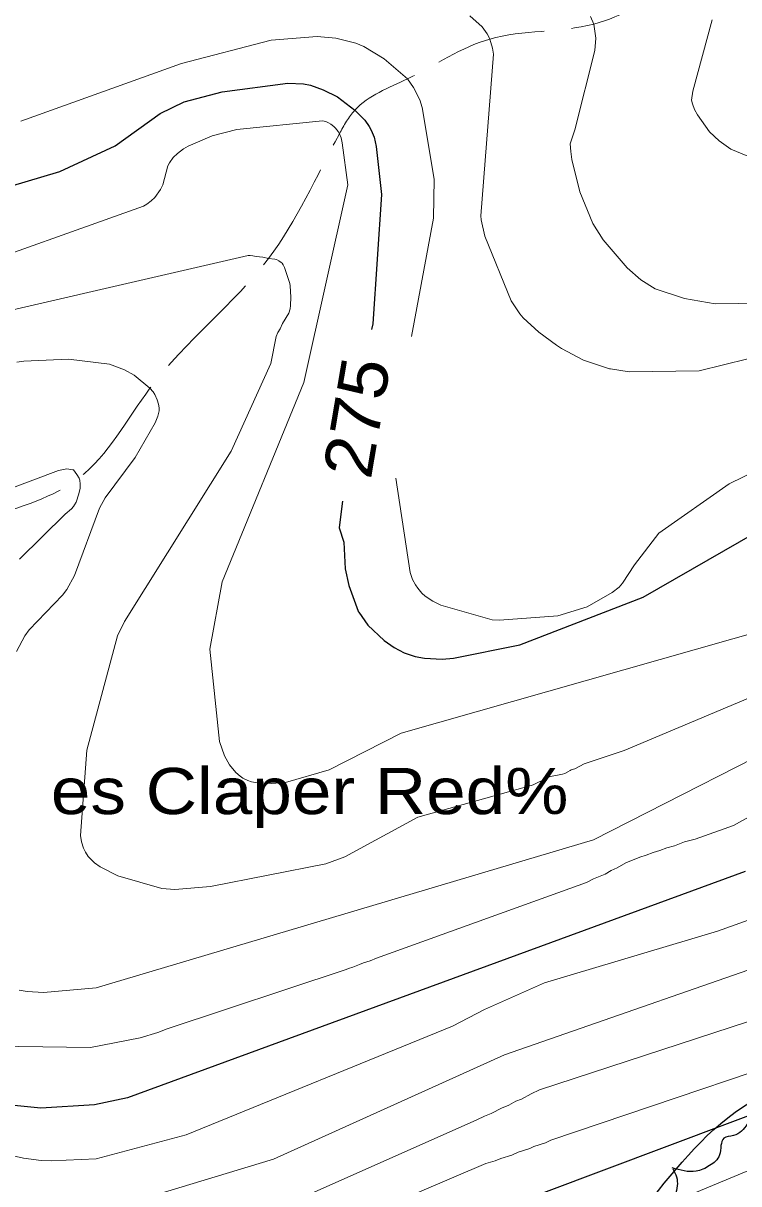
# Model space of a CAD drawing. Extents: x 483847 to 488453, y 4383581 to 4386795.
# Drawn here: x 484426.1 to 484573.2, y 4385231.8 to 4385470.4 of the extents above; entities that cross this region are included whole.
import ezdxf
from ezdxf.enums import TextEntityAlignment as Align

# ---------------------------------------------------------------- set-up
doc = ezdxf.new("R2010")
doc.units = 0
doc.header["$LTSCALE"] = 3.8
doc.linetypes.add('LONG_DASHED', pattern=[7.5, 6, -1.5])
for name, color, linetype, lineweight in [('15', 7, 'LONG_DASHED', 13), ('27', 7, 'Continuous', 25), ('8', 7, 'Continuous', 25), ('9', 7, 'Continuous', 13)]:
    doc.layers.add(name, color=color, linetype=linetype, lineweight=lineweight)
doc.layers.add('5', color=7, linetype='Continuous')

msp = doc.modelspace()

# ---------------------------------------------------------------- linework, layer by layer
at = {"layer": '15'}
for points in [[(484350.85, 4385309.99), (484355.46, 4385318.85), (484367.84, 4385329.38), (484393.13, 4385346.87), (484401.36, 4385359.26), (484437.57, 4385376.85), (484452.16, 4385395.32), (484476.51, 4385422), (484491.08, 4385447.61), (484494.26, 4385452.51), (484505.09, 4385458.92), (484521.99, 4385467.1), (484543.39, 4385470.17), (484559.79, 4385478.44)], [(484440.86, 4385107.33), (484415.84, 4385135.05), (484384.62, 4385161.06), (484370.39, 4385170.61), (484355.4, 4385205.72), (484344.92, 4385223.18), (484340.8, 4385245.79), (484346.02, 4385267.08), (484346.62, 4385276.73), (484350.56, 4385302.69), (484348.32, 4385334.77), (484339.19, 4385362.03), (484342.51, 4385396.83), (484345.88, 4385416.04)]]:
    msp.add_spline(points, degree=3, dxfattribs=at)
at = {"layer": '27'}
for points in [[(484126.09, 4384902.79), (484170.42, 4384940.62), (484186.72, 4384951.71), (484191.28, 4384949.75), (484195.85, 4384942.58), (484195.2, 4384850.61), (484198.46, 4384849.31), (484203.02, 4384849.96), (484206.93, 4384851.91), (484210.19, 4384864.31), (484210.19, 4384911.92), (484211.5, 4384943.23), (484214.1, 4384965.41), (484221.93, 4384987.58), (484217.36, 4384992.8), (484210.19, 4384992.8), (484135.22, 4384984.97), (484130.65, 4384988.89), (484126.09, 4384997.37), (484121.53, 4385047.59), (484126.09, 4385059.33), (484133.91, 4385067.16), (484151.52, 4385069.77), (484197.15, 4385061.94), (484225.84, 4385054.77), (484236.92, 4385050.2), (484251.92, 4385040.42), (484272.13, 4385031.28), (484285.82, 4385029.98), (484298.2, 4385029.33), (484332.11, 4385039.76), (484352.32, 4385052.16), (484358.18, 4385050.2), (484379.05, 4385045.63), (484396, 4385044.98), (484413.6, 4385057.38), (484413.6, 4385076.29), (484415.56, 4385110.21), (484421.42, 4385117.38), (484434.46, 4385125.86), (484452.06, 4385127.17), (484517.26, 4385131.08), (484535.51, 4385145.43), (484539.43, 4385153.26), (484534.21, 4385163.04), (484527.69, 4385172.17), (484530.3, 4385183.26), (484560.29, 4385234.79), (484583.76, 4385251.75), (484588.32, 4385252.4), (484664.6, 4385247.83), (484699.15, 4385252.4), (484722.1, 4385262.06)], [(484575.75, 4385249.41), (484576.09, 4385247.67), (484574.93, 4385244.05), (484572.09, 4385241.69), (484570.12, 4385241.12), (484569.21, 4385237.68), (484567.18, 4385235.49), (484564.39, 4385234.33), (484559.48, 4385235.05)], [(484559.63, 4385234.8), (484560.37, 4385233.18), (484560.09, 4385229.4), (484557.89, 4385226.44), (484556.11, 4385225.41), (484556.03, 4385221.86), (484554.57, 4385219.25), (484552.13, 4385217.47), (484547.19, 4385217.02)]]:
    msp.add_spline(points, degree=3, dxfattribs=at)
at = {"layer": '8'}
for points in [[(484423.28, 4385436.77), (484433.61, 4385439.88), (484445, 4385445.12), (484445.01, 4385445.13), (484454.27, 4385451.81), (484459.21, 4385454.18), (484466.98, 4385456.26), (484480.51, 4385458.01), (484483.73, 4385457.93), (484485.14, 4385457.61), (484487.77, 4385456.69), (484490.68, 4385455.19), (484494.26, 4385452.51), (484496.29, 4385450.43), (484497.23, 4385449.1), (484497.65, 4385448.35), (484498.23, 4385446.95), (484498.67, 4385445.04), (484499.72, 4385435.13), (484497.95, 4385408.54), (484497.67, 4385407.36)], [(484495.33, 4385215.76), (484621.58, 4385263.2), (484631.09, 4385269.88), (484651.45, 4385288.45), (484664.71, 4385298.03), (484677.35, 4385304.64), (484708.83, 4385315.8), (484709.67, 4385315.88), (484736.51, 4385325.19), (484796.07, 4385353.34), (484802.99, 4385358.9), (484824.15, 4385384.06), (484827.81, 4385387.03), (484835.85, 4385392.05), (484953.02, 4385435.42), (484996.6, 4385457.39)], [(484491.97, 4385363.65), (484492.28, 4385358.19), (484493.04, 4385354.76), (484494.95, 4385349.48), (484494.96, 4385349.44), (484495.05, 4385349.27), (484496.92, 4385346.58), (484500.26, 4385343.43), (484502.32, 4385342.04), (484504.42, 4385340.91), (484506.68, 4385340.14), (484508.55, 4385339.81), (484512.2, 4385339.59), (484514.52, 4385339.79), (484528.16, 4385342.56), (484553.54, 4385352.35), (484642.85, 4385403.67)], [(484491.7, 4385372.11), (484491.02, 4385366.67), (484491.02, 4385366.66), (484491.05, 4385366.59), (484491.97, 4385363.65)], [(484574.52, 4385295.99), (484447.53, 4385249.4), (484440.77, 4385248.01), (484429.73, 4385247.29), (484422.86, 4385247.96)]]:
    msp.add_lwpolyline(points, dxfattribs=at)
at = {"layer": '9'}
for points in [[(484547.16, 4385353.32), (484548.62, 4385354.44), (484549.3, 4385355.23), (484551.72, 4385358.98), (484556.73, 4385365.52), (484571.23, 4385375.65), (484690, 4385433.69), (484706.46, 4385445.99), (484801.19, 4385492.21), (484829.57, 4385515.57), (484909.23, 4385559.67), (484917.52, 4385566), (484938.51, 4385586.77), (484945.08, 4385596.55), (484953.79, 4385606.66), (484958.11, 4385610.46), (484997.78, 4385639.17)], [(484517.87, 4385471.85), (484520.4, 4385469.62), (484521.44, 4385468.21), (484521.8, 4385467.54), (484521.99, 4385467.1), (484522.55, 4385465.23), (484522.73, 4385464.02), (484520.13, 4385430.79), (484520.24, 4385429.96), (484520.99, 4385426.6), (484526.41, 4385413.29), (484528.17, 4385410.58), (484528.89, 4385409.76), (484532.09, 4385406.81), (484535.7, 4385404.18), (484536.77, 4385403.47)], [(484542.67, 4385471.73), (484543.39, 4385470.17), (484543.76, 4385467.29), (484543.62, 4385464.78), (484539.58, 4385448.68), (484539.55, 4385448.62), (484538.51, 4385445.59), (484538.65, 4385443.98)], [(484567.7, 4385471.06), (484563.73, 4385456.37), (484563.47, 4385454.57), (484563.64, 4385453.8), (484564.09, 4385452.61), (484564.67, 4385451.52), (484567.15, 4385448.05), (484569.17, 4385446.16), (484571.54, 4385444.49), (484575.03, 4385443.02)], [(484425.64, 4385450.19), (484458.66, 4385462.1), (484477.07, 4385466.88), (484486.52, 4385467.61), (484490.35, 4385467.27), (484494.48, 4385466.24), (484496.08, 4385465.55), (484500.29, 4385463.05), (484505.09, 4385458.92), (484506.35, 4385457.16), (484507.62, 4385454.62), (484508.11, 4385453.02), (484510.55, 4385438.28), (484510.42, 4385430.27), (484505.94, 4385405.96)], [(484410.39, 4385418.35), (484450.81, 4385432.72), (484451.51, 4385433.14), (484452.43, 4385433.85), (484453.12, 4385434.56), (484454.31, 4385436.17), (484454.81, 4385437.15), (484455.81, 4385441.01), (484456.14, 4385441.67), (484456.94, 4385442.73), (484457.82, 4385443.6), (484459.07, 4385444.56), (484460.01, 4385445.08), (484464.94, 4385447.21), (484470.04, 4385448.54), (484487.63, 4385450.29), (484488.27, 4385450.14), (484488.86, 4385449.9), (484489.3, 4385449.63), (484489.94, 4385449.13), (484490.31, 4385448.75), (484490.81, 4385448.09), (484491.08, 4385447.61)], [(484491.08, 4385447.61), (484491.42, 4385446.81), (484491.66, 4385445.76), (484492.81, 4385437.1), (484483.8, 4385396.49), (484466.97, 4385355.53), (484464.44, 4385341.68), (484466.45, 4385322.71), (484467.5, 4385319.73), (484468.53, 4385317.9), (484469.78, 4385316.34), (484470.66, 4385315.58), (484471.27, 4385315.16), (484472.3, 4385314.67), (484473.01, 4385314.43), (484474.23, 4385314.18), (484477.04, 4385314.02), (484479.99, 4385314.23), (484489.01, 4385316.88), (484503.81, 4385324.39), (484587.37, 4385348.16)], [(484538.65, 4385443.98), (484538.86, 4385442.36), (484540.48, 4385435.71), (484543.16, 4385429.2), (484545.33, 4385425.82), (484550.24, 4385420.07), (484553.01, 4385417.63), (484556, 4385415.75), (484562.02, 4385413.73), (484568.29, 4385412.7), (484577.75, 4385412.81)], [(484441.58, 4385225.93), (484477.54, 4385236.81), (484524.99, 4385258.28), (484589.22, 4385280.63), (484600.96, 4385288.16), (484637.94, 4385317.48), (484657.13, 4385329.47), (484671.15, 4385335.82), (484721.52, 4385353.32), (484742.93, 4385362.89), (484751.52, 4385368.08), (484830.88, 4385429.46), (484833.4, 4385430.86)], [(484971.71, 4385429.08), (484909.59, 4385406.14), (484895.88, 4385400.07), (484876.32, 4385394.93), (484872.33, 4385393.3), (484794.9, 4385341.15), (484701.15, 4385297.85), (484680.43, 4385289.98), (484678.09, 4385288.82), (484653.07, 4385268.42), (484646.79, 4385264.26), (484558.06, 4385227.37)], [(484438.08, 4385302.03), (484437.85, 4385303.38), (484439.17, 4385320.91), (484445.46, 4385344.41), (484446.92, 4385347.37), (484468.81, 4385382.37), (484476.97, 4385400.42), (484478.09, 4385405.93), (484478.44, 4385406.78), (484478.9, 4385407.53), (484479.39, 4385408.64), (484480.67, 4385410.72), (484480.95, 4385411.62), (484481.05, 4385412.34), (484481.12, 4385414.04), (484480.95, 4385416.37), (484480.87, 4385416.84), (484479.8, 4385420.13), (484479.56, 4385420.68), (484479.31, 4385421.01), (484479.12, 4385421.18), (484478.67, 4385421.51), (484478.14, 4385421.77), (484477.85, 4385421.86), (484476.51, 4385422), (484475.32, 4385422.29), (484473.98, 4385422.4), (484473.31, 4385422.55), (484472.72, 4385422.63), (484472.34, 4385422.61), (484402.55, 4385406.5)], [(484536.77, 4385403.47), (484541.27, 4385401.06), (484546.63, 4385399.3), (484546.81, 4385399.29), (484550.62, 4385398.69), (484565.05, 4385398.88), (484575.02, 4385401.38)], [(484424.69, 4385341.22), (484426.44, 4385344.41), (484427.33, 4385345.64), (484434.2, 4385352.76), (484435.09, 4385353.95), (484436.67, 4385356.83), (484441.76, 4385370.68), (484442.92, 4385372.76), (484449.11, 4385381.08), (484453.21, 4385388.2), (484453.78, 4385389.54), (484454.02, 4385390.7), (484454.04, 4385391.28), (484453.92, 4385392.01), (484453.63, 4385392.92), (484453.14, 4385394.01), (484452.79, 4385394.57), (484452.16, 4385395.32), (484448.91, 4385397.99), (484446.95, 4385399.13), (484443.84, 4385400.23), (484435.38, 4385401.31), (484426.21, 4385400.86), (484424.82, 4385400.65)], [(484425.36, 4385360.19), (484434.71, 4385369.43), (484436, 4385370.53), (484436.45, 4385371.02), (484436.65, 4385371.32), (484436.96, 4385371.92), (484437.56, 4385373.62), (484437.79, 4385374.77), (484437.83, 4385375.59), (484437.73, 4385376.41), (484437.57, 4385376.85), (484437.13, 4385377.59), (484436.43, 4385378.52), (484436.33, 4385378.55), (484435.04, 4385378.73), (484433.34, 4385378.37), (484413.25, 4385370.88)], [(484502.68, 4385376.85), (484505.63, 4385357.41), (484506.13, 4385355.99), (484506.7, 4385354.89), (484507.19, 4385354.18), (484508.05, 4385353.17), (484508.75, 4385352.54), (484510.29, 4385351.51), (484511.95, 4385350.74), (484522.52, 4385347.73), (484524.02, 4385347.65), (484535.98, 4385348.51), (484541.99, 4385350.4), (484547.16, 4385353.32)], [(484582.02, 4385334.5), (484549.64, 4385320.84), (484541.37, 4385318.08), (484539.51, 4385317.1), (484538.74, 4385316.84), (484538.51, 4385316.73), (484538.04, 4385316.43), (484537.39, 4385316.11), (484536.92, 4385315.96), (484534.5, 4385315.49), (484534.26, 4385315.42), (484533.59, 4385315.11), (484530.93, 4385313.79), (484530.52, 4385313.65), (484507.22, 4385307.14), (484492.19, 4385299.01), (484488.3, 4385297.56), (484464.57, 4385292.91), (484457.24, 4385292.27), (484454.59, 4385292.45), (484445.56, 4385295.07), (484441.89, 4385296.92), (484440.74, 4385297.75), (484439.78, 4385298.67), (484439.45, 4385299.06), (484438.91, 4385299.94), (484438.51, 4385300.78), (484438.08, 4385302.03)], [(484590.93, 4385326.71), (484543.3, 4385302.48), (484441.11, 4385272.02), (484430.26, 4385271.11), (484426.94, 4385271.3), (484425.26, 4385271.56)], [(484592.04, 4385316.55), (484572.12, 4385305.45), (484564.24, 4385302.62), (484562.01, 4385302.04), (484559.93, 4385301.25), (484558.38, 4385300.82), (484556.95, 4385300.27), (484555.57, 4385299.87), (484554.14, 4385299.3), (484552.81, 4385298.88), (484549.97, 4385297.71), (484548.17, 4385296.71), (484546.92, 4385296.17), (484545.7, 4385295.43), (484543.34, 4385294.48), (484541.87, 4385293.69), (484498.72, 4385278.16), (484497.38, 4385277.57), (484496.01, 4385277.16), (484495.25, 4385276.83), (484494.53, 4385276.6), (484493.84, 4385276.3), (484492.98, 4385276), (484492.49, 4385275.78), (484455.66, 4385263.63), (484453.77, 4385262.83), (484450.12, 4385261.79), (484439.92, 4385259.75), (484415.35, 4385260.13)], [(484441.13, 4385236.9), (484459.56, 4385241.84), (484514.35, 4385264.18), (484520.93, 4385267.6), (484533.26, 4385273.1), (484568.77, 4385283.69), (484584.28, 4385289.27)], [(484593.19, 4385271.05), (484532.25, 4385251.05), (484530.47, 4385250.25), (484528.53, 4385249.17), (484527.33, 4385248.73), (484525.94, 4385247.92), (484525.8, 4385247.85), (484524.56, 4385247.39), (484522.29, 4385246.19), (484520.91, 4385245.68), (484519.33, 4385244.94), (484483.47, 4385228.97)], [(484488.76, 4385222.12), (484521.18, 4385235.91), (484523.07, 4385236.48), (484524.3, 4385236.98), (484526.5, 4385237.65), (484527.8, 4385238.25), (484530.2, 4385239.01), (484531.03, 4385239.42), (484533.42, 4385240.17), (484534.54, 4385240.74), (484601.87, 4385263.45)], [(484421.57, 4385238.06), (484426.15, 4385237.02), (484429.81, 4385236.55), (484431.86, 4385236.46), (484441.13, 4385236.9)]]:
    msp.add_lwpolyline(points, dxfattribs=at)

# ---------------------------------------------------------------- texts
at = {"layer": '5', "width": 1.15}
msp.add_text('es Claper Red%', height=9.5, dxfattribs=at).set_placement((484538.16, 4385307.76), align=Align.RIGHT)
at = {"layer": '8', "width": 1.1}
msp.add_text('275', height=10, rotation=80.356, dxfattribs=at).set_placement((484499.58, 4385388.45), align=Align.CENTER)

doc.saveas('drawing.dxf')
